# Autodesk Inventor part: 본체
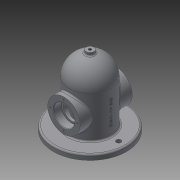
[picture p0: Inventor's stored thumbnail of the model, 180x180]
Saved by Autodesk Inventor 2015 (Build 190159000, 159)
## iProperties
Created: 2019-11
Part Number: 본체
Material: 일반
Document SubType Name: Modeling
Designer: Line503_02
Density: 1 g/cm^3
Appearance: 기본값
Author: Line503_02
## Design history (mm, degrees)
sketch "스케치1"
  geometry: L1 (-40, 0)-(-40, -90); L2 (-40, -90)-(0, -90); L3 (0, 40)-(0, -90); A1 r 40 centre (0, 0) between (0, 40) and (-40, 0); 1 further point
  constraints: 6 end point, 2 point on circle, 2 vertical, 1 centre point, 1 coincident, 1 horizontal, 1 tangent
  dimensions: "d0" = 40 radius of A1; "d1" = 90 distance of L1.start L1.end; "d2" = 130 distance of L3.start L2.end
revolve "회전1" sketch "스케치1" stored, may be unused: angle "d3" = 90 deg
feature "쉘1" dims "d4" = 10
node "작업 평면1"
sketch "스케치2"
  geometry: L1 (40, -90)-(-40, -90) reference; C1 r 31 at (0, -40); 1 further point
  constraints: 1 centre point, 1 vertical alignment
  dimensions: "d6" = 62 diameter of C1; "d7" = 50 distance from line of L1 C1.centre
extrude "돌출1" join sketch "스케치2" stored distance "d8" = 10; taper "d9" = 0 deg
hole "구멍1" diameter "d12" = 33; stored, may be unused: countersink angle "d16" = 90 deg, drill point angle "d18" = 118 deg; dims "d10" = 10, "d11" = 10, "d13" = 6, "d14" = 40, "d15" = 15, "d17" = 8
sketch "스케치3"
  geometry: C1 r 20 at (0, 0) reference; 2 further points
  constraints: 1 horizontal alignment
  dimensions: "d19" = 26 distance of point (26, 0) C1.centre
hole "구멍2" sketch "스케치3" at (26, 0) diameter "d20" = 3.242; stored, may be unused: countersink angle "d24" = 90 deg, drill point angle "d26" = 118 deg; dims "d21" = 8, "d22" = 40, "d23" = 15, "d25" = 10
sketch "스케치4"
  geometry: C1 r 70 at (0, 0); C2 r 30 at (0, 0); C3 r 40 at (0, 0) reference; C4 r 30 at (0, 0) reference; C5 r 4.5 at (55, 0); C6 r 4.5 at (-55, 0); 1 further point
  constraints: 4 centre point, 2 coincident, 2 equal radius, 2 horizontal alignment
  dimensions: "d30" = 140 diameter of C1; "d31" = 9 diameter of C5; "d32" = 110 distance of C6.centre C5.centre; "d33" = 55 distance of point (0, 0) C5.centre (= 0.5 x d32)
extrude "돌출2" join sketch "스케치4" distance "d34" = 10; taper "d35" = 0 deg
node "작업 평면2"
sketch "스케치5"
  geometry: C1 r 7.5 at (0, 0); 1 further point
  constraints: 1 centre point, 1 coincident
  dimensions: "d37" = 15 diameter of C1
extrude "돌출3" join sketch "스케치5" stored distance "d38" = 10; taper "d39" = 0 deg
hole "구멍3" diameter "d42" = 5.188; stored, may be unused: countersink angle "d46" = 90 deg, drill point angle "d48" = 118 deg; dims "d40" = 10, "d41" = 10, "d43" = 12, "d44" = 40, "d45" = 15, "d47" = 16
fillet "모깎기1" dims "d49" = 3, "d50" = 0.3
chamfer "모따기1" distance "d51" = 1; stored, may be unused: second distance "d52" = 2, angle "d53" = 45 deg
node "작업 평면3"
sketch "스케치6"
  geometry: L1 (70, -45)-(-70, -45) reference; 2 further points
  constraints: 1 vertical alignment, 1 other
  dimensions: "d54" = 50 distance from line of point (0, 5) L1
feature "엠보싱1" sketch "스케치6" dims "d0" = 40, "d1" = 90, "d2" = 130, "d55" = 0.5, "d56" = 0
node "솔리드1"
pattern_circular "원형 패턴1" dims angle "d28" = 360 deg
mirror "대칭1"
other parameters: "d36" = -135
